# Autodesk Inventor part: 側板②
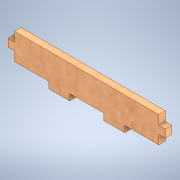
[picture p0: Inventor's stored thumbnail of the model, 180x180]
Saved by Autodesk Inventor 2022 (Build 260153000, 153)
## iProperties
Created: 2024-11
Part Number: 側板②
Material: MDF 中密度繊維ボード
Document SubType Name: Modeling
Designer: shimizu
Density: 0.8 g/cm^3
Appearance: サクラ材 - ナチュラル 抑えた光沢
Author: shimizu
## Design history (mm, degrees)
sketch "スケッチ1"
  geometry: L1 (-25.358, 1.343)-(29.642, 1.343); L2 (-4.358, -8.657)-(-4.358, -11.157); L3 (-4.358, -11.157)-(-12.358, -11.157); L4 (-12.358, -11.157)-(-12.358, -8.657); L5 (16.642, -8.657)-(16.642, -11.157); L6 (16.642, -11.157)-(8.642, -11.157); L7 (8.642, -11.157)-(8.642, -8.657); L8 (-25.358, -2.157)-(-27.858, -2.157); L9 (-27.858, -2.157)-(-27.858, -5.157); L10 (-27.858, -5.157)-(-25.358, -5.157); L11 (29.642, -2.157)-(32.142, -2.157); L12 (32.142, -2.157)-(32.142, -5.157); L13 (32.142, -5.157)-(29.642, -5.157); L14 (-25.358, -8.657)-(-25.358, -5.157); L15 (-25.358, -2.157)-(-25.358, 1.343); L16 (29.642, 1.343)-(29.642, -2.157); L17 (29.642, -5.157)-(29.642, -8.657); L18 (29.642, -8.657)-(16.642, -8.657); L19 (8.642, -8.657)-(-4.358, -8.657); L20 (-12.358, -8.657)-(-25.358, -8.657); 1 further point
  constraints: 40 end point, 11 parallel, 4 perpendicular, 3 horizontal
  dimensions: "d16" = 13 distance of L17.end L5.start; "d17" = 13 distance of L4.end L14.start; "d18" = 8 distance of L5.end L6.end; "d19" = 8 distance of L2.end L3.end; "d20" = 13 distance of L7.end L2.start; "d21" = 55 distance between parallel lines of L16 L15; "d22" = 60 distance between parallel lines of L12 L9
extrude "押し出し1" new body sketch "スケッチ1" distance "d14" = 2.5; taper "d15" = 0 deg
node "ソリッド1"
